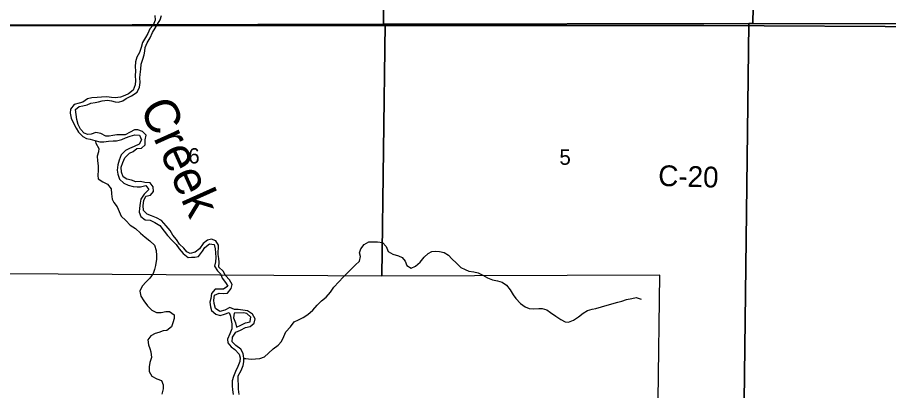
# Model space of a CAD drawing. Extents: x 1772825 to 1773716, y 1138558 to 1139032.
# Drawn here: x 1772827.997 to 1772829.187, y 1138560.637 to 1138561.147 of the extents above; entities that cross this region are included whole.
import ezdxf

# ---------------------------------------------------------------- set-up
doc = ezdxf.new("R2010")
doc.units = 0
for name, color, linetype in [('GM_X_County_Road_Text', 7, 'Continuous'), ('GM_X_Major_River', 7, 'Continuous'), ('GM_X_Major_River_Text', 7, 'Continuous'), ('GM_X_Minor_River', 7, 'Continuous'), ('GM_X_Section', 7, 'Continuous'), ('GM_X_Section_Text', 7, 'Continuous'), ('GM_X_Township', 7, 'Continuous')]:
    doc.layers.add(name, color=color, linetype=linetype)

msp = doc.modelspace()

# ---------------------------------------------------------------- linework, layer by layer
at = {"layer": 'GM_X_Major_River'}
for points in [[(1772828.1853, 1138561.1498), (1772828.1856, 1138561.1432), (1772828.1827, 1138561.1366), (1772828.1783, 1138561.1315), (1772828.1754, 1138561.1252), (1772828.1723, 1138561.1196), (1772828.1681, 1138561.1126), (1772828.1664, 1138561.106), (1772828.1642, 1138561.0993), (1772828.1604, 1138561.0929), (1772828.1588, 1138561.0863), (1772828.1584, 1138561.0795), (1772828.1585, 1138561.0742), (1772828.1583, 1138561.0673), (1772828.1586, 1138561.0609), (1772828.1584, 1138561.0548), (1772828.1557, 1138561.0478), (1772828.149, 1138561.0427), (1772828.1442, 1138561.0405), (1772828.138, 1138561.0381), (1772828.1307, 1138561.0372), (1772828.1258, 1138561.0376), (1772828.1196, 1138561.0384), (1772828.1122, 1138561.0383), (1772828.1065, 1138561.0376), (1772828.0989, 1138561.0374), (1772828.0932, 1138561.0358), (1772828.0867, 1138561.0311), (1772828.0819, 1138561.0298), (1772828.0751, 1138561.0279), (1772828.0699, 1138561.0217), (1772828.0695, 1138561.0164), (1772828.0706, 1138561.0092), (1772828.0741, 1138561.0027), (1772828.0777, 1138560.9958), (1772828.0809, 1138560.9903), (1772828.0867, 1138560.9842), (1772828.0918, 1138560.9815), (1772828.0967, 1138560.9805), (1772828.1032, 1138560.9788), (1772828.1098, 1138560.9772), (1772828.1155, 1138560.977), (1772828.1218, 1138560.9779), (1772828.128, 1138560.9784), (1772828.1328, 1138560.9785), (1772828.1398, 1138560.9804), (1772828.1451, 1138560.9824), (1772828.1514, 1138560.985), (1772828.1577, 1138560.9865), (1772828.164, 1138560.9863), (1772828.1668, 1138560.98), (1772828.1639, 1138560.9738), (1772828.1568, 1138560.9708), (1772828.1503, 1138560.968), (1772828.1452, 1138560.9654), (1772828.1391, 1138560.9593), (1772828.1364, 1138560.9521), (1772828.1346, 1138560.9455), (1772828.1338, 1138560.9385), (1772828.1345, 1138560.933), (1772828.1369, 1138560.9262), (1772828.1426, 1138560.9208), (1772828.1488, 1138560.9179), (1772828.1555, 1138560.916), (1772828.1608, 1138560.9157), (1772828.1655, 1138560.9157), (1772828.1729, 1138560.9173), (1772828.1769, 1138560.9118), (1772828.1706, 1138560.9058), (1772828.1662, 1138560.8988), (1772828.1652, 1138560.8931), (1772828.164, 1138560.8863), (1772828.1637, 1138560.881), (1772828.1658, 1138560.8749), (1772828.172, 1138560.8705), (1772828.1787, 1138560.8701), (1772828.1849, 1138560.8668), (1772828.1917, 1138560.8628), (1772828.1979, 1138560.8551), (1772828.2024, 1138560.8492), (1772828.2088, 1138560.8423), (1772828.2143, 1138560.8366), (1772828.2184, 1138560.8309), (1772828.2237, 1138560.8244), (1772828.2305, 1138560.819), (1772828.2352, 1138560.8196), (1772828.2399, 1138560.8197), (1772828.2447, 1138560.8204), (1772828.2503, 1138560.8276), (1772828.2535, 1138560.8325), (1772828.2596, 1138560.8376), (1772828.2661, 1138560.8366), (1772828.2674, 1138560.8311), (1772828.2679, 1138560.8254), (1772828.2686, 1138560.8191), (1772828.268, 1138560.813), (1772828.2668, 1138560.807)], [(1772828.2719, 1138560.8358), (1772828.2682, 1138560.8419), (1772828.2625, 1138560.8442), (1772828.2572, 1138560.8427), (1772828.2511, 1138560.838), (1772828.2461, 1138560.8309), (1772828.2402, 1138560.8262), (1772828.2335, 1138560.8245), (1772828.2286, 1138560.8268), (1772828.2245, 1138560.8316), (1772828.219, 1138560.8373), (1772828.2147, 1138560.8436), (1772828.2096, 1138560.8495), (1772828.2061, 1138560.8558), (1772828.2006, 1138560.8621), (1772828.1944, 1138560.8696), (1772828.1874, 1138560.8732), (1772828.1806, 1138560.8761), (1772828.1747, 1138560.8781), (1772828.1698, 1138560.8834), (1772828.1691, 1138560.8901), (1772828.1701, 1138560.8971), (1772828.1728, 1138560.9027), (1772828.1791, 1138560.904), (1772828.1835, 1138560.9091), (1772828.183, 1138560.9158), (1772828.1787, 1138560.9211), (1772828.1714, 1138560.9213), (1772828.1654, 1138560.9231), (1772828.1593, 1138560.9222), (1772828.1533, 1138560.9247), (1772828.147, 1138560.9259), (1772828.1419, 1138560.9292), (1772828.1395, 1138560.9358), (1772828.1392, 1138560.9423), (1772828.1413, 1138560.9489), (1772828.1442, 1138560.9553), (1772828.1503, 1138560.9617), (1772828.1553, 1138560.964), (1772828.1606, 1138560.9679), (1772828.1671, 1138560.9686), (1772828.1718, 1138560.9731), (1772828.1721, 1138560.9798), (1772828.1733, 1138560.986), (1772828.1682, 1138560.991), (1772828.1621, 1138560.9935), (1772828.1574, 1138560.9935), (1772828.1513, 1138560.9902), (1772828.1444, 1138560.9868), (1772828.1382, 1138560.9867), (1772828.1334, 1138560.9865), (1772828.1279, 1138560.9856), (1772828.1228, 1138560.9849), (1772828.118, 1138560.9847), (1772828.1112, 1138560.9884), (1772828.1046, 1138560.99), (1772828.0983, 1138560.9877), (1772828.0936, 1138560.987), (1772828.0886, 1138560.9887), (1772828.0836, 1138560.9945), (1772828.0806, 1138561.0009), (1772828.0787, 1138561.0078), (1772828.0776, 1138561.0146), (1772828.0769, 1138561.0211), (1772828.0819, 1138561.0252), (1772828.0866, 1138561.0261), (1772828.0927, 1138561.0278), (1772828.0977, 1138561.0297), (1772828.1034, 1138561.0306), (1772828.1081, 1138561.0317), (1772828.1131, 1138561.0331), (1772828.1203, 1138561.0342), (1772828.126, 1138561.0329), (1772828.1309, 1138561.0315), (1772828.1356, 1138561.0313), (1772828.1413, 1138561.0333), (1772828.1461, 1138561.0361), (1772828.1532, 1138561.0397), (1772828.161, 1138561.0451), (1772828.1642, 1138561.0517), (1772828.1649, 1138561.058), (1772828.1647, 1138561.0644), (1772828.1649, 1138561.0692), (1772828.1658, 1138561.0762), (1772828.1666, 1138561.083), (1772828.1687, 1138561.09), (1772828.1706, 1138561.0957), (1772828.1714, 1138561.101), (1772828.1719, 1138561.1061), (1772828.1748, 1138561.1125), (1772828.1786, 1138561.1192), (1772828.1821, 1138561.1263), (1772828.1857, 1138561.1322), (1772828.1886, 1138561.1379), (1772828.1922, 1138561.1437), (1772828.194, 1138561.1496)], [(1772828.3004, 1138560.6318), (1772828.2993, 1138560.6392), (1772828.2994, 1138560.6457), (1772828.2988, 1138560.6512), (1772828.2989, 1138560.6576), (1772828.3029, 1138560.6648), (1772828.3056, 1138560.6716), (1772828.3066, 1138560.6766), (1772828.3068, 1138560.6813), (1772828.3058, 1138560.6878), (1772828.3024, 1138560.694), (1772828.2958, 1138560.699), (1772828.2905, 1138560.7038), (1772828.2913, 1138560.7102), (1772828.2959, 1138560.7169), (1772828.3022, 1138560.72), (1772828.3089, 1138560.7232), (1772828.3153, 1138560.7247), (1772828.3209, 1138560.7292), (1772828.322, 1138560.7354), (1772828.3183, 1138560.7415), (1772828.3117, 1138560.7461), (1772828.3051, 1138560.7473), (1772828.299, 1138560.7479), (1772828.2941, 1138560.7482), (1772828.2874, 1138560.7509), (1772828.2806, 1138560.7473), (1772828.2737, 1138560.7455), (1772828.2679, 1138560.7493), (1772828.266, 1138560.756), (1772828.2655, 1138560.7607), (1772828.2667, 1138560.7675), (1772828.2728, 1138560.7705), (1772828.2794, 1138560.7699), (1772828.2842, 1138560.7702), (1772828.2895, 1138560.7768), (1772828.2907, 1138560.782), (1772828.287, 1138560.7884), (1772828.2815, 1138560.7945), (1772828.2785, 1138560.8006), (1772828.2727, 1138560.806), (1772828.2729, 1138560.8128), (1772828.2726, 1138560.8178), (1772828.2718, 1138560.8231), (1772828.2719, 1138560.8358)], [(1772828.2668, 1138560.807), (1772828.2705, 1138560.8009), (1772828.2754, 1138560.7963), (1772828.2769, 1138560.7908), (1772828.2814, 1138560.7851), (1772828.2846, 1138560.7799), (1772828.2789, 1138560.776), (1772828.2721, 1138560.776), (1772828.2673, 1138560.7759), (1772828.2627, 1138560.7698), (1772828.2615, 1138560.763), (1772828.2604, 1138560.7579), (1772828.2609, 1138560.7516), (1772828.2626, 1138560.7467), (1772828.2686, 1138560.7417), (1772828.2745, 1138560.7396), (1772828.2804, 1138560.7418), (1772828.2864, 1138560.7439), (1772828.2885, 1138560.7391), (1772828.2892, 1138560.733), (1772828.2903, 1138560.7283), (1772828.2903, 1138560.7214), (1772828.2876, 1138560.7146), (1772828.2845, 1138560.7076), (1772828.2848, 1138560.7023), (1772828.2893, 1138560.6972), (1772828.2942, 1138560.6933), (1772828.3001, 1138560.6872), (1772828.3015, 1138560.6821), (1772828.3011, 1138560.677), (1772828.2984, 1138560.67), (1772828.2951, 1138560.6634), (1772828.2926, 1138560.6567), (1772828.2909, 1138560.6507), (1772828.2908, 1138560.6439), (1772828.291, 1138560.6384), (1772828.2921, 1138560.6317)], [(1772828.3158, 1138560.7352), (1772828.316, 1138560.7376), (1772828.3109, 1138560.7427), (1772828.306, 1138560.7435), (1772828.2933, 1138560.7429)], [(1772828.2933, 1138560.7429), (1772828.2926, 1138560.7368), (1772828.2951, 1138560.7299), (1772828.2965, 1138560.7239), (1772828.3024, 1138560.7267), (1772828.3089, 1138560.7297), (1772828.3154, 1138560.7311), (1772828.3158, 1138560.7352)]]:
    msp.add_lwpolyline(points, dxfattribs=at)
at = {"layer": 'GM_X_Minor_River'}
for points in [[(1772828.1035, 1138560.9787), (1772828.1043, 1138560.9753), (1772828.1086, 1138560.9681), (1772828.1082, 1138560.9632), (1772828.1064, 1138560.9575), (1772828.107, 1138560.951), (1772828.1079, 1138560.9442), (1772828.1076, 1138560.9383), (1772828.1074, 1138560.9313), (1772828.1075, 1138560.9266), (1772828.1142, 1138560.9222), (1772828.1206, 1138560.9191), (1772828.1253, 1138560.9128), (1772828.1258, 1138560.9061), (1772828.1269, 1138560.8989), (1772828.1289, 1138560.8942), (1772828.1338, 1138560.8882), (1772828.1362, 1138560.882), (1772828.1389, 1138560.8755), (1772828.1454, 1138560.8696), (1772828.1515, 1138560.8633), (1772828.1585, 1138560.8586), (1772828.1654, 1138560.8525), (1772828.1717, 1138560.847), (1772828.1783, 1138560.8416), (1772828.1847, 1138560.8357), (1772828.1871, 1138560.8286), (1772828.1876, 1138560.822), (1772828.1872, 1138560.8169), (1772828.1858, 1138560.8082), (1772828.1846, 1138560.8025), (1772828.1829, 1138560.7974), (1772828.1784, 1138560.7906), (1772828.1733, 1138560.7857), (1772828.1679, 1138560.78), (1772828.1648, 1138560.7732), (1772828.1659, 1138560.7662), (1772828.1703, 1138560.7599), (1772828.1749, 1138560.753), (1772828.181, 1138560.7473), (1772828.1872, 1138560.7437), (1772828.1937, 1138560.7438), (1772828.2003, 1138560.7451), (1772828.2052, 1138560.7452), (1772828.2115, 1138560.7406), (1772828.2114, 1138560.7359), (1772828.2095, 1138560.7296), (1772828.2077, 1138560.7245), (1772828.2016, 1138560.7193), (1772828.1967, 1138560.7187), (1772828.1904, 1138560.7165), (1772828.1857, 1138560.7152), (1772828.1798, 1138560.7122), (1772828.1755, 1138560.7064), (1772828.1766, 1138560.6999), (1772828.1783, 1138560.6948), (1772828.1798, 1138560.69), (1772828.1807, 1138560.6826), (1772828.1784, 1138560.6758), (1772828.1774, 1138560.6696), (1772828.1773, 1138560.6633), (1772828.1811, 1138560.657), (1772828.1877, 1138560.6534), (1772828.1941, 1138560.651), (1772828.1963, 1138560.6451), (1772828.1965, 1138560.6396), (1772828.1945, 1138560.6324)], [(1772828.3068, 1138560.681), (1772828.3093, 1138560.6809), (1772828.3165, 1138560.6803), (1772828.3226, 1138560.6806), (1772828.3287, 1138560.6811), (1772828.3349, 1138560.6832), (1772828.3405, 1138560.6882), (1772828.3468, 1138560.6943), (1772828.3537, 1138560.6993), (1772828.3581, 1138560.7044), (1772828.3615, 1138560.7112), (1772828.3638, 1138560.7177), (1772828.3703, 1138560.7243), (1772828.3753, 1138560.731), (1772828.3814, 1138560.7337), (1772828.3877, 1138560.7372), (1772828.3942, 1138560.7413), (1772828.4007, 1138560.747), (1772828.407, 1138560.7539), (1772828.4129, 1138560.76), (1772828.4192, 1138560.765), (1772828.425, 1138560.7715), (1772828.4298, 1138560.7784), (1772828.4363, 1138560.7858), (1772828.4424, 1138560.7922), (1772828.4473, 1138560.7971), (1772828.4525, 1138560.8024), (1772828.4586, 1138560.8084), (1772828.4647, 1138560.814), (1772828.4659, 1138560.8205), (1772828.4648, 1138560.8254), (1772828.4664, 1138560.8309), (1772828.4708, 1138560.8367), (1772828.4776, 1138560.8403), (1772828.4843, 1138560.8406), (1772828.4894, 1138560.8406), (1772828.496, 1138560.8394), (1772828.5011, 1138560.8339), (1772828.5039, 1138560.8274), (1772828.5103, 1138560.8234), (1772828.5181, 1138560.8212), (1772828.523, 1138560.8189), (1772828.527, 1138560.8141), (1772828.5294, 1138560.808), (1772828.5353, 1138560.8044), (1772828.5413, 1138560.8072), (1772828.5473, 1138560.8128), (1772828.553, 1138560.8196), (1772828.5585, 1138560.8243), (1772828.5633, 1138560.8271), (1772828.5684, 1138560.8277), (1772828.5739, 1138560.8274), (1772828.5802, 1138560.826), (1772828.5862, 1138560.8222), (1772828.5907, 1138560.8172), (1772828.597, 1138560.8113), (1772828.603, 1138560.8054), (1772828.6089, 1138560.8025), (1772828.6138, 1138560.8006), (1772828.6206, 1138560.7996), (1772828.6267, 1138560.798), (1772828.6329, 1138560.7949), (1772828.6395, 1138560.7915), (1772828.6461, 1138560.7887), (1772828.6529, 1138560.7874), (1772828.6594, 1138560.7854), (1772828.6654, 1138560.7814), (1772828.6705, 1138560.7751), (1772828.6746, 1138560.768), (1772828.678, 1138560.7629), (1772828.6844, 1138560.756), (1772828.6908, 1138560.7516), (1772828.6963, 1138560.7495), (1772828.7018, 1138560.7489), (1772828.7094, 1138560.7496), (1772828.7143, 1138560.7492), (1772828.7206, 1138560.7474), (1772828.7257, 1138560.7441), (1772828.7328, 1138560.7388), (1772828.7396, 1138560.7342), (1772828.7455, 1138560.7313), (1772828.7502, 1138560.7309), (1772828.7571, 1138560.7335), (1772828.7636, 1138560.738), (1772828.7699, 1138560.7429), (1772828.7762, 1138560.7466), (1772828.7822, 1138560.7485), (1772828.7876, 1138560.7492), (1772828.795, 1138560.7516), (1772828.7997, 1138560.7529), (1772828.8047, 1138560.7544), (1772828.8123, 1138560.7568), (1772828.8176, 1138560.7582), (1772828.8231, 1138560.7593), (1772828.8292, 1138560.7618), (1772828.8364, 1138560.7632), (1772828.8427, 1138560.7643), (1772828.8493, 1138560.7622)]]:
    msp.add_lwpolyline(points, dxfattribs=at)
at = {"layer": 'GM_X_Section'}
for points in [[(1772827.9835, 1138561.6464), (1772828.5028, 1138561.6436), (1772828.4973, 1138561.1378), (1772827.9825, 1138561.1365), (1772827.9834, 1138561.6394)], [(1772828.5028, 1138561.6436), (1772829.0119, 1138561.6398), (1772829.002, 1138561.1389), (1772828.9965, 1138561.1389), (1772828.4997, 1138561.1379), (1772828.4973, 1138561.1378)], [(1772829.5079, 1138561.639), (1772829.4984, 1138561.1377), (1772829.002, 1138561.1389), (1772829.0119, 1138561.6398)], [(1772828.4973, 1138561.1378), (1772828.4997, 1138561.1379), (1772828.4951, 1138560.7937), (1772827.9793, 1138560.7967), (1772827.9825, 1138561.1365)], [(1772828.4997, 1138561.1379), (1772828.9965, 1138561.1389), (1772828.9898, 1138560.6225), (1772828.8725, 1138560.6245), (1772828.8749, 1138560.7948), (1772828.4951, 1138560.7937)], [(1772828.9965, 1138561.1389), (1772829.002, 1138561.1389), (1772829.4984, 1138561.1377), (1772829.4949, 1138560.6247), (1772828.9898, 1138560.6225)]]:
    msp.add_lwpolyline(points, close=True, dxfattribs=at)
at = {"layer": 'GM_X_Township'}
for points in [[(1772829.265, 1138561.1343), (1772828.9351, 1138561.1362), (1772828.7389, 1138561.1358), (1772828.3739, 1138561.1358), (1772827.9826, 1138561.1355), (1772827.9839, 1138561.2587)], [(1772829.3568, 1138558.1226), (1772828.6597, 1138558.1236), (1772828.4654, 1138558.1239), (1772828.0428, 1138558.1245), (1772827.9602, 1138558.1247), (1772827.9658, 1138558.8741), (1772827.9695, 1138559.3784), (1772827.9733, 1138559.6274), (1772827.9734, 1138559.8049), (1772827.972, 1138559.9153), (1772827.9742, 1138560.1264), (1772827.9761, 1138560.4021), (1772827.9772, 1138560.5798), (1772827.9826, 1138561.1355), (1772828.3739, 1138561.1358), (1772828.7389, 1138561.1358), (1772828.9351, 1138561.1362), (1772829.265, 1138561.1343)]]:
    msp.add_lwpolyline(points, dxfattribs=at)

# ---------------------------------------------------------------- texts
at = {"layer": 'GM_X_County_Road_Text'}
msp.add_text('C-20', height=0.02841, rotation=358.2744, dxfattribs=at).set_placement((1772828.8723, 1138560.9169))
at = {"layer": 'GM_X_Major_River_Text'}
msp.add_text('Creek', height=0.04737, rotation=294.2225, dxfattribs=at).set_placement((1772828.1639, 1138561.0244))
at = {"layer": 'GM_X_Section_Text'}
for s, p in [('6', (1772828.2308, 1138560.9475)), ('5', (1772828.7377, 1138560.9457))]:
    msp.add_text(s, height=0.0209, rotation=0, dxfattribs=at).set_placement(p)

doc.saveas('drawing.dxf')
